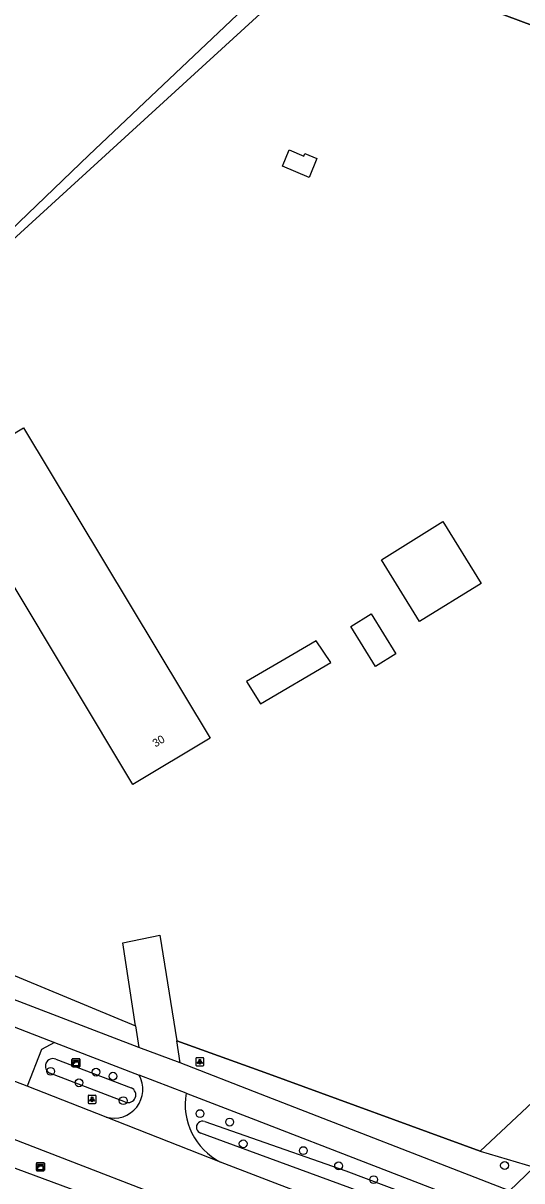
# Model space of a CAD drawing. Extents: x 155209 to 156823, y 385356 to 388482.
# Drawn here: x 155762.9 to 155825.2, y 386710.5 to 386855.1 of the extents above; entities that cross this region are included whole.
import ezdxf

# ---------------------------------------------------------------- set-up
doc = ezdxf.new("R2010")
doc.units = 0
for name, color, linetype in [('IMGEO_Berm_groen', 7, 'Continuous'), ('IMGEO_Boom', 7, 'Continuous'), ('IMGEO_Fietspad_gesloten', 7, 'Continuous'), ('IMGEO_Gemengd_bos', 7, 'Continuous'), ('IMGEO_Hek', 7, 'Continuous'), ('IMGEO_Kast', 7, 'Continuous'), ('IMGEO_Lichtpunt', 7, 'Continuous'), ('IMGEO_Pand', 7, 'Continuous'), ('IMGEO_Pand_nummerreeks', 7, 'Continuous'), ('IMGEO_Rijbaan_lokaal_gesloten', 7, 'Continuous'), ('IMGEO_Rijbaan_lokaal_open', 7, 'Continuous'), ('IMGEO_Voetpad_open', 7, 'Continuous'), ('IMGEO_Waterloop', 7, 'Continuous')]:
    doc.layers.add(name, color=color, linetype=linetype)

msp = doc.modelspace()

# ---------------------------------------------------------------- linework, layer by layer
at = {"layer": 'IMGEO_Berm_groen'}
for points in [[(155696.05, 386763.44), (155728.33, 386750), (155776.91, 386729.81)], [(155782.08, 386727.97), (155793.53, 386723.81), (155820.02, 386714.17)], [(155820.02, 386714.17), (155826.78, 386712.15)], [(155823.67, 386709.23), (155826.78, 386712.15)]]:
    msp.add_lwpolyline(points, dxfattribs=at)
at = {"layer": 'IMGEO_Boom'}
for centre in [(155766.32, 386724.14), (155771.99, 386724.04), (155769.86, 386722.71), (155774.11, 386723.53), (155775.39, 386720.47), (155784.99, 386718.86), (155788.7, 386717.8), (155790.39, 386715.09), (155797.9, 386714.24), (155802.31, 386712.33), (155823.06, 386712.38), (155806.7, 386710.61)]:
    msp.add_circle(centre, 0.489, dxfattribs=at)
at = {"layer": 'IMGEO_Fietspad_gesloten'}
for points in [[(155777.32, 386727.1), (155717.68, 386750), (155664.94, 386770.25)], [(155761.76, 386729.68), (155766.81, 386727.74)], [(155766.81, 386727.74), (155777.37, 386723.68)], [(155823.67, 386709.23), (155792.56, 386721.3), (155782.52, 386725.2)], [(155783.26, 386721.41), (155791.39, 386718.27), (155821.98, 386706.46)]]:
    msp.add_lwpolyline(points, dxfattribs=at)
at = {"layer": 'IMGEO_Gemengd_bos'}
for points in [[(155820.02, 386714.17), (155895.67, 386784.96), (155927.56, 386817.29), (155801.22, 386864.26), (155757.67, 386824.49), (155759.61, 386822.37), (155696.05, 386763.44)], [(155711.43, 386781.69), (155736.11, 386805.05), (155771.1, 386838.59), (155794.24, 386860.52), (155798.1, 386864.18)]]:
    msp.add_lwpolyline(points, dxfattribs=at)
at = {"layer": 'IMGEO_Hek'}
for points in [[(155696.05, 386763.44), (155759.61, 386822.37), (155757.67, 386824.49), (155801.22, 386864.26), (155927.56, 386817.29), (155895.67, 386784.96), (155820.02, 386714.17)], [(155820.02, 386714.17), (155793.53, 386723.81), (155782.08, 386727.97)]]:
    msp.add_lwpolyline(points, dxfattribs=at)
at = {"layer": 'IMGEO_Kast'}
for p, q in [((155768.98, 386724.78), (155768.98, 386725.62)), ((155768.98, 386725.62), (155768.98, 386724.78)), ((155769.06, 386725.71), (155769.9, 386725.71)), ((155769.9, 386725.71), (155769.06, 386725.71)), ((155769.91, 386724.71), (155769.07, 386724.71)), ((155769.07, 386724.71), (155769.91, 386724.71)), ((155769.98, 386725.63), (155769.98, 386724.79)), ((155769.98, 386724.79), (155769.98, 386725.63)), ((155764.6, 386712.72), (155765.45, 386712.72)), ((155765.45, 386712.72), (155764.6, 386712.72)), ((155764.53, 386711.8), (155764.53, 386712.64)), ((155764.53, 386712.64), (155764.53, 386711.8)), ((155765.46, 386711.73), (155764.61, 386711.73)), ((155764.61, 386711.73), (155765.46, 386711.73)), ((155765.53, 386712.65), (155765.53, 386711.81)), ((155765.53, 386711.81), (155765.53, 386712.65))]:
    msp.add_line(p, q, dxfattribs=at)
for points in [[(155769.18, 386725.5), (155769.78, 386725.5), (155769.78, 386725.41), (155769.18, 386725.41), (155769.18, 386725.5)], [(155769.18, 386725.32), (155769.78, 386725.32), (155769.78, 386724.84), (155769.18, 386724.84), (155769.18, 386725.32)], [(155764.73, 386712.52), (155765.33, 386712.52), (155765.33, 386712.43), (155764.73, 386712.43), (155764.73, 386712.52)], [(155764.73, 386712.34), (155765.33, 386712.34), (155765.33, 386711.85), (155764.73, 386711.85), (155764.73, 386712.34)]]:
    msp.add_lwpolyline(points, dxfattribs=at)
for centre in [(155769.26, 386725.17), (155764.81, 386712.19)]:
    msp.add_circle(centre, 0.0377, dxfattribs=at)
for centre, start, end in [((155769.06, 386725.63), 92.4484, 184.2845), ((155769.06, 386725.63), 92.4484, 184.2845), ((155769.06, 386724.79), 182.4484, 274.2845), ((155769.06, 386724.79), 182.4484, 274.2845), ((155769.91, 386725.63), 2.4484, 94.2845), ((155769.91, 386725.63), 2.4484, 94.2845), ((155769.91, 386724.79), 272.4484, 4.2845), ((155769.91, 386724.79), 272.4484, 4.2845), ((155764.61, 386712.65), 92.4484, 184.2845), ((155764.61, 386712.65), 92.4484, 184.2845), ((155765.45, 386712.65), 2.4484, 94.2845), ((155765.45, 386712.65), 2.4484, 94.2845), ((155764.61, 386711.8), 182.4484, 274.2845), ((155764.61, 386711.8), 182.4484, 274.2845), ((155765.45, 386711.8), 272.4484, 4.2845), ((155765.45, 386711.8), 272.4484, 4.2845)]:
    msp.add_arc(centre, 0.0779, start, end, dxfattribs=at)
at = {"layer": 'IMGEO_Lichtpunt'}
for p, q in [((155784.47, 386725.74), (155784.47, 386724.93)), ((155784.47, 386725.74), (155784.47, 386724.93)), ((155785.37, 386725.83), (155784.56, 386725.83)), ((155785.37, 386725.83), (155784.56, 386725.83)), ((155785.46, 386724.93), (155785.46, 386725.74)), ((155785.46, 386724.93), (155785.46, 386725.74)), ((155784.56, 386724.83), (155785.37, 386724.83)), ((155784.56, 386724.83), (155785.37, 386724.83)), ((155771, 386721.05), (155771, 386720.24)), ((155771, 386721.05), (155771, 386720.24)), ((155771.9, 386721.14), (155771.09, 386721.14)), ((155771.9, 386721.14), (155771.09, 386721.14)), ((155771.09, 386720.14), (155771.9, 386720.14)), ((155771.09, 386720.14), (155771.9, 386720.14)), ((155771.99, 386720.24), (155771.99, 386721.05)), ((155771.99, 386720.24), (155771.99, 386721.05))]:
    msp.add_line(p, q, dxfattribs=at)
for points in [[(155784.84, 386725.4), (155784.88, 386725.37), (155784.69, 386725.11), (155784.65, 386725.14), (155784.84, 386725.4)], [(155784.94, 386725.35), (155784.99, 386725.35), (155784.99, 386725.03), (155784.94, 386725.03), (155784.94, 386725.35)], [(155785.05, 386725.37), (155785.09, 386725.4), (155785.28, 386725.14), (155785.24, 386725.11), (155785.05, 386725.37)], [(155771.37, 386720.71), (155771.41, 386720.68), (155771.22, 386720.42), (155771.18, 386720.45), (155771.37, 386720.71)], [(155771.47, 386720.66), (155771.52, 386720.66), (155771.52, 386720.34), (155771.47, 386720.34), (155771.47, 386720.66)], [(155771.58, 386720.68), (155771.62, 386720.71), (155771.81, 386720.45), (155771.77, 386720.42), (155771.58, 386720.68)]]:
    msp.add_lwpolyline(points, dxfattribs=at)
for centre in [(155784.97, 386725.53), (155771.5, 386720.84)]:
    msp.add_circle(centre, 0.0994, dxfattribs=at)
for centre, start, end in [((155784.56, 386725.74), 90, 180), ((155784.56, 386725.74), 90, 180), ((155785.37, 386725.74), 0, 90), ((155785.37, 386725.74), 0, 90), ((155784.56, 386724.93), 180, 270), ((155784.56, 386724.93), 180, 270), ((155785.37, 386724.93), 270, 0), ((155785.37, 386724.93), 270, 360), ((155771.09, 386721.05), 90, 180), ((155771.09, 386721.05), 90, 180), ((155771.09, 386720.24), 180, 270), ((155771.09, 386720.24), 180, 270), ((155771.9, 386721.05), 0, 90), ((155771.9, 386721.05), 0, 90), ((155771.9, 386720.24), 270, 0), ((155771.9, 386720.24), 270, 360)]:
    msp.add_arc(centre, 0.0946, start, end, dxfattribs=at)
at = {"layer": 'IMGEO_Pand'}
for points in [[(155795.29, 386837.22), (155796.14, 386839.26), (155797.97, 386838.48), (155798.1, 386838.78), (155799.61, 386838.16), (155798.64, 386835.82), (155795.29, 386837.22)], [(155776.61, 386759.96), (155753.28, 386798.76), (155762.92, 386804.55), (155786.24, 386765.75), (155776.61, 386759.96)], [(155812.44, 386780.35), (155807.67, 386788.05), (155815.36, 386792.81), (155820.12, 386785.1), (155812.44, 386780.35)], [(155809.48, 386776.29), (155806.92, 386774.7), (155803.83, 386779.7), (155806.39, 386781.29), (155809.48, 386776.29)], [(155792.55, 386770.03), (155801.35, 386775.21), (155799.51, 386777.93), (155796.59, 386776.21), (155790.81, 386772.82), (155792.55, 386770.03)]]:
    msp.add_lwpolyline(points, dxfattribs=at)
at = {"layer": 'IMGEO_Rijbaan_lokaal_gesloten'}
for points in [[(155763.39, 386722.27), (155760.55, 386723.38)], [(155783.26, 386721.41), (155777.37, 386723.68)], [(155773.27, 386718.42), (155763.39, 386722.27)], [(155787.54, 386712.8), (155773.27, 386718.42)], [(155761.51, 386715.74), (155786.7, 386706.02), (155810.97, 386696.65)], [(155818.26, 386701.02), (155787.54, 386712.8)]]:
    msp.add_lwpolyline(points, dxfattribs=at)
for centre, radius, start, end in [((155774.23, 386721.9), 3.61, 254.598, 29.5253), ((155791.26, 386720.03), 8.13, 170.1841, 242.7489)]:
    msp.add_arc(centre, radius, start, end, dxfattribs=at)
at = {"layer": 'IMGEO_Rijbaan_lokaal_open'}
for points in [[(155776.91, 386729.81), (155775.36, 386740.2), (155779.95, 386741.14), (155782.08, 386727.97)], [(155776.91, 386729.81), (155777.32, 386727.1)], [(155782.52, 386725.2), (155782.08, 386727.97)], [(155782.52, 386725.2), (155777.32, 386727.1)]]:
    msp.add_lwpolyline(points, dxfattribs=at)
at = {"layer": 'IMGEO_Voetpad_open'}
msp.add_lwpolyline([(155766.81, 386727.74), (155765.18, 386726.86), (155763.39, 386722.27)], dxfattribs=at)
at = {"layer": 'IMGEO_Waterloop'}
for points in [[(155766.96, 386725.67), (155776.4, 386722.08)], [(155775.69, 386720.3), (155766.22, 386723.92)], [(155785.57, 386717.88), (155790.57, 386716.13), (155803.21, 386711.7), (155818.46, 386705.97), (155817.55, 386704.28), (155803.73, 386709.57), (155789.98, 386714.61), (155785.11, 386716.4)], [(155808.7, 386694.05), (155785.63, 386703.2), (155783.77, 386703.93), (155761.11, 386712.3), (155761.07, 386712.32)]]:
    msp.add_lwpolyline(points, dxfattribs=at)
for centre, radius, start, end in [((155766.61, 386724.78), 0.951, 68.5692, 245.6669), ((155776.01, 386721.2), 0.958, 250.1617, 66.1132), ((155785.31, 386717.15), 0.776, 71.0764, 254.4358)]:
    msp.add_arc(centre, radius, start, end, dxfattribs=at)

# ---------------------------------------------------------------- texts
at = {"layer": 'IMGEO_Pand_nummerreeks'}
msp.add_text('30', height=1, rotation=31.0171, dxfattribs=at).set_placement((155779.42, 386764.59))

doc.saveas('drawing.dxf')
